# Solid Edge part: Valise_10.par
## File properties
Author: Bernard DUMAS
Template: Normal.par
Last saved by: FR026244
Revision: 6
Application: Solid Edge
Material: Bois, Chêne
Style de face: Jaune kaki
Style de remplissage: Liège
Style virtuel: Chêne verni
Coef. of Thermal Exp: 0.0
Thermal Conductivity: 0.0
Specific Heat: 0.0
Modulus of Elasticity: 0.0
Poission's Ratio: 0.0
Yield Stress: 0.0
Ultimate Stress: 0.0
Elongation: 0.0
Densité: 631.000 kg/m^3
Précision: 0.9900
Document Number: 10
Revision: a
Project Name: Slamson
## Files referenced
..\Valise_Salmson.asm
bD:\Documents and Settings\FR026244\Mes Documents\Bernard\Slamson\Valise-Salmson\Valise_Salmson.asm
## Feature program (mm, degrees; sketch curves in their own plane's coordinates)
sketch for "unnamed Protrusion 1" plane through (0, 0, 0) normal (0, -1, 0) x-axis (1, 0, 0)
  line (6, 78) -> (6, 113)
  line (6, 113) -> (443.2918, 113)
  line (460.7918, 78) -> (443.2918, 113)
  line (6, 78) -> (460.7918, 78)
extrude "unnamed Protrusion 1" add finite 4 along +normal
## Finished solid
Body 1: solid body, 6 faces, 12 edges, 8 vertices.
  Faces by surface: plane 6
  Edges by curve: line 12
Bounding box of the edges (mm): 454.792 x 4.000 x 35.000, from (6, -4, 78) to (460.7918, 0, 113).
Planar faces by outward normal: +y 1, +z 1, -x 1, -y 1, -z 1, oblique 1
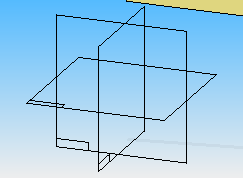
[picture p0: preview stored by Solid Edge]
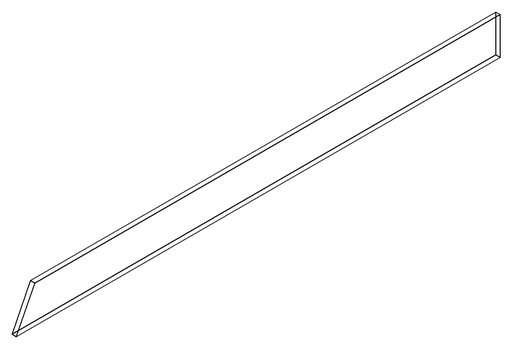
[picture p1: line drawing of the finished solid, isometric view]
